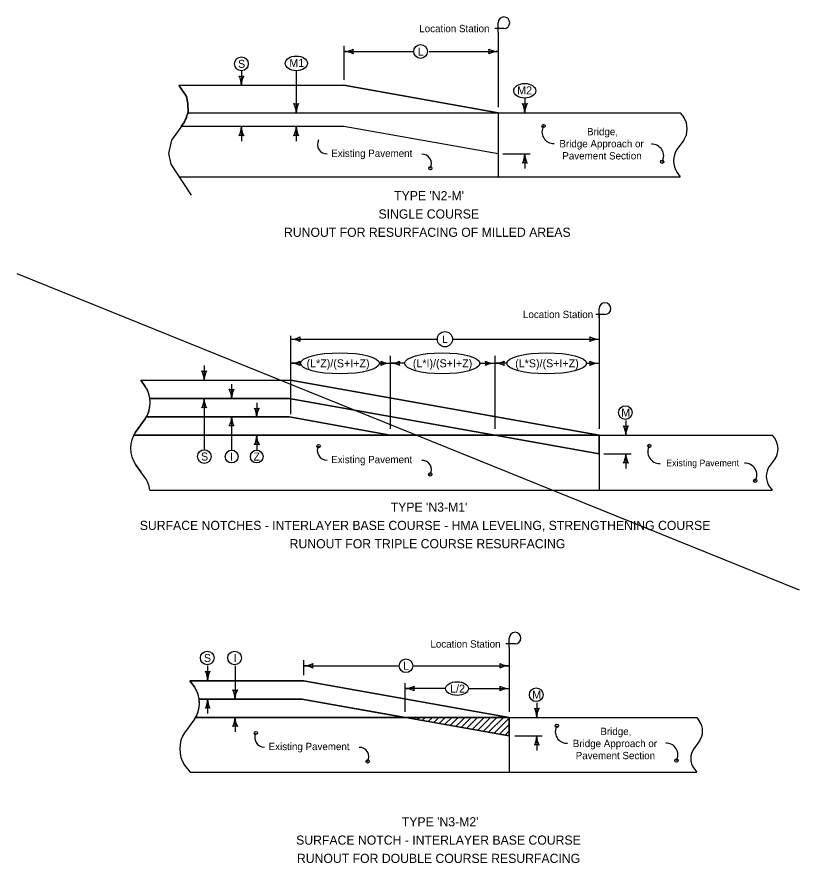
# Model space of a CAD drawing. Extents: x 10133 to 81668, y 2218 to 11018.
# Drawn here: x 14300 to 16011, y 5339 to 7189 of the extents above; entities that cross this region are included whole.
import ezdxf

# ---------------------------------------------------------------- set-up
doc = ezdxf.new("R2010")
doc.units = 0
for name, color, linetype in [('Default', 7, 'Continuous'), ('dsnNonPlotable', 7, 'Continuous'), ('dsnShtPlotShapeBatchPrint', 7, 'Continuous'), ('dsnStdBlock', 7, 'Continuous'), ('dsnStdBlockNotModified', 7, 'Continuous'), ('Level 2', 7, 'Continuous'), ('SheetBorder', 7, 'Continuous')]:
    doc.layers.add(name, color=color, linetype=linetype)

msp = doc.modelspace()

# ---------------------------------------------------------------- linework, layer by layer
at = {"layer": 'Default'}
for points in [[(14688, 5724.1), (14678.2, 5737.5), (14926.8, 5737.5), (15376.8, 5657.5), (15148.3, 5657.5), (14923.3, 5697.5), (14698.2, 5697.5)], [(15150.3, 5657.1), (15376.8, 5616.9), (15376.8, 5657.5), (15150.6, 5657.5), (15150.3, 5657.1)]]:
    msp.add_lwpolyline(points, dxfattribs=at)
msp.add_ellipse((14662.1, 5688.7), major_axis=(0, -50), ratio=0.732645, start_param=1.746494, end_param=2.356194, dxfattribs=at)
at = {"layer": 'dsnNonPlotable'}
for p, q in [((14580.4, 6381.2), (14570.6, 6394.6)), ((14570.6, 6394.6), (14898.5, 6394.6)), ((14898.5, 6394.6), (15573.5, 6274.6)), ((14895, 6354.6), (14590.5, 6354.6)), ((14590.5, 6354.6), (14590.6, 6354.6)), ((14590.5, 6354.6), (14895, 6354.6)), ((15345, 6274.6), (14895, 6354.6)), ((14895, 6354.6), (15345, 6274.6)), ((14559, 6281.2), (14580.4, 6310.5)), ((14580.4, 6310.5), (14580.4, 6310.5)), ((14895, 6314.6), (14583.1, 6314.6)), ((14583.1, 6314.6), (14895, 6314.6)), ((15116.5, 6274.6), (14895, 6314.6)), ((14895, 6314.6), (15116.5, 6274.6)), ((15116.5, 6274.6), (14554.9, 6274.6)), ((15345, 6274.6), (15116.5, 6274.6)), ((15573.5, 6274.6), (15345, 6274.6))]:
    msp.add_line(p, q, dxfattribs=at)
msp.add_lwpolyline([(14666.4, 6959.6), (14674.1, 6980.4), (14673.8, 6999.6), (14670.5, 7015), (14653.9, 7039.6), (15015, 7039.6), (15352.5, 6979.6), (15352.5, 6889.6), (15015, 6949.6), (14659.2, 6949.6)], close=True, dxfattribs=at)
for points in [[(15345, 6274.6), (15573.5, 6234), (15573.5, 6274.6), (15347.3, 6274.6), (15345, 6274.6)], [(14698.2, 5697.5), (14923.3, 5697.5), (15148.3, 5657.5), (14690.7, 5657.5)]]:
    msp.add_lwpolyline(points, dxfattribs=at)
for centre, major_axis, start_param, end_param in [((14554.5, 6345.9), (0, -50), 1.746494, 2.356194), ((14554.5, 6345.9), (0, -50), 0.895403, 1.746494), ((14554.5, 6345.9), (0, -50), 0.785398, 0.895403), ((14584.9, 6245.9), (0, 50), 0.785398, 0.958442), ((14662.1, 5688.7), (0, -50), 0.895403, 1.746494)]:
    msp.add_ellipse(centre, major_axis=major_axis, ratio=0.732645, start_param=start_param, end_param=end_param, dxfattribs=at)
at = {"layer": 'dsnStdBlock'}
for p, q in [((15365.2, 7163.8), (15344.9, 7163.8)), ((15352.5, 7156.1), (15352.5, 7176.5)), ((15352.5, 7156.1), (15352.5, 6991.6)), ((15015, 7125.6), (15015, 7051.6)), ((15015, 7113.6), (15166.3, 7113.6)), ((15201.3, 7113.6), (15352.5, 7113.6)), ((14790.7, 7071.6), (14790.7, 7039.6)), ((14910.7, 7071.6), (14910.7, 6979.6)), ((14653.9, 7039.6), (15015, 7039.6)), ((15352.5, 6979.6), (15015, 7039.6)), ((15410.7, 7011.6), (15410.7, 6979.6)), ((14673.5, 6979.6), (15015, 6979.6)), ((15352.5, 6979.6), (15352.5, 6839.6)), ((15352.5, 6979.6), (15751, 6979.6)), ((15352.5, 6979.6), (15352.5, 6839.6)), ((15751, 6979.6), (15758.5, 6969.3)), ((15015, 6949.6), (14659.2, 6949.6)), ((14790.7, 6949.6), (14790.7, 6917.6)), ((14910.7, 6949.6), (14910.7, 6917.6)), ((15352.5, 6889.6), (15015, 6949.6)), ((15758.5, 6919.8), (15743.5, 6899.3)), ((15362.7, 6889.6), (15422.7, 6889.6)), ((15410.7, 6889.6), (15410.7, 6857.6)), ((15743.5, 6849.8), (15751, 6839.6)), ((14653.9, 6839.6), (15751, 6839.6)), ((15573.5, 6530.9), (15573.5, 6551.3)), ((15586.2, 6538.6), (15565.9, 6538.6)), ((15573.5, 6538.6), (15573.5, 6288.4)), ((14898.5, 6491.5), (14898.5, 6400.6)), ((14899.6, 6484.4), (15219.4, 6484.4)), ((15252.7, 6484.4), (15573.5, 6484.4)), ((15116.5, 6448.4), (15116.5, 6288.4)), ((15345, 6448.4), (15345, 6288.4)), ((14709.3, 6426.9), (14709.3, 6394.9)), ((14920.1, 6431.7), (14898.5, 6431.7)), ((15092.7, 6431.7), (15116.5, 6431.7)), ((15147.9, 6431.7), (15116.5, 6431.7)), ((15312.3, 6431.7), (15345, 6431.7)), ((15371.3, 6431.7), (15345, 6431.7)), ((15545.8, 6431.7), (15573.5, 6431.7)), ((14570.6, 6394.6), (14580.4, 6381.2)), ((14570.6, 6394.6), (14898.5, 6394.6)), ((14769.2, 6386.3), (14769.2, 6354.3)), ((14898.5, 6400.6), (14898.5, 6320.4)), ((15573.5, 6274.6), (14898.5, 6394.6)), ((14590.5, 6354.6), (14895, 6354.6)), ((14709.3, 6354.6), (14709.3, 6242.5)), ((15573.5, 6234), (14895, 6354.6)), ((14824.2, 6345.2), (14824.2, 6313.2)), ((14580.4, 6310.5), (14559, 6281.2)), ((14583.1, 6314.6), (14895, 6314.6)), ((14769.3, 6315), (14769.3, 6241.9)), ((15116.5, 6274.6), (14895, 6314.6)), ((15631.7, 6306.6), (15631.7, 6274.6)), ((14554.9, 6274.6), (15951.9, 6274.6)), ((14824.3, 6273.9), (14824.3, 6241.9)), ((15345, 6274.6), (15345, 6274.6)), ((15345, 6274.6), (15573.5, 6274.6)), ((15345.7, 6274.5), (15345.9, 6274.6)), ((15346.9, 6274.3), (15347.3, 6274.6)), ((15348.5, 6274.6), (15903, 6274.6)), ((15350.5, 6273.6), (15351.4, 6274.6)), ((15573.5, 6274.6), (15573.5, 6234)), ((15951.9, 6274.6), (15958.4, 6265.8)), ((15573.5, 6234), (15573.5, 6154.6)), ((15583.7, 6234), (15643.7, 6234)), ((15631.7, 6234), (15631.7, 6202)), ((15958.4, 6223.4), (15945.5, 6205.8)), ((14580.4, 6181.2), (14559, 6210.6)), ((14559, 6210.5), (14571, 6194.6)), ((15945.5, 6163.4), (15951.9, 6154.6)), ((14590.6, 6154.6), (15951.9, 6154.6)), ((15376.8, 5810.5), (15376.8, 5830.8)), ((15389.5, 5818.1), (15369.2, 5818.1)), ((15376.8, 5810.5), (15376.8, 5669.5)), ((14926.8, 5782.5), (14926.8, 5749.5)), ((14716.8, 5769.9), (14716.8, 5737.9)), ((14776.8, 5769.9), (14776.8, 5697.5)), ((14926.8, 5770.5), (15135.8, 5770.5)), ((15165.8, 5770.5), (15376.8, 5770.5)), ((14678.2, 5737.5), (14688, 5724.1)), ((14678.2, 5737.5), (14926.8, 5737.5)), ((14927.3, 5737.4), (14678.2, 5737.5)), ((15376.8, 5657.5), (14926.8, 5737.5)), ((15148.3, 5732.5), (15148.3, 5669.5)), ((15237.6, 5720.5), (15148.3, 5720.5)), ((15287.6, 5720.5), (15376.8, 5720.5)), ((14698.2, 5697.5), (14923.3, 5697.5)), ((14716.8, 5697.9), (14716.8, 5665.9)), ((15376.8, 5616.9), (14923.3, 5697.5)), ((15436.8, 5689.5), (15436.8, 5657.5)), ((14688, 5653.4), (14666.5, 5624.1)), ((14690.7, 5657.5), (15376.8, 5657.5)), ((14776.8, 5657.9), (14776.8, 5625.9)), ((15148.3, 5657.5), (15148.3, 5657.5)), ((15148.3, 5657.5), (15376.8, 5657.5)), ((15149.1, 5657.3), (15149.2, 5657.5)), ((15150.3, 5657.1), (15150.6, 5657.5)), ((15163.4, 5654.8), (15166.1, 5657.5)), ((15168.2, 5653.9), (15171.7, 5657.5)), ((15175.4, 5652.7), (15180.2, 5657.5)), ((15186.2, 5650.7), (15193, 5657.5)), ((15199.4, 5648.4), (15208.5, 5657.5)), ((15211.4, 5646.3), (15222.7, 5657.5)), ((15223.4, 5644.1), (15236.8, 5657.5)), ((15235.4, 5642), (15250.9, 5657.5)), ((15247.5, 5639.9), (15265.1, 5657.5)), ((15259.5, 5637.7), (15279.2, 5657.5)), ((15271.5, 5635.6), (15293.4, 5657.5)), ((15283.5, 5633.5), (15307.5, 5657.5)), ((15295.5, 5631.3), (15321.6, 5657.5)), ((15307.5, 5629.2), (15335.8, 5657.5)), ((15319.5, 5627), (15349.9, 5657.5)), ((15331.5, 5624.9), (15364.1, 5657.5)), ((15343.5, 5622.8), (15376.8, 5656.1)), ((15376.8, 5657.5), (15786.8, 5657.5)), ((15376.8, 5657.5), (15376.8, 5616.9)), ((15786.8, 5657.5), (15793.3, 5648.7)), ((15355.5, 5620.6), (15376.8, 5642)), ((15367.5, 5618.5), (15376.8, 5627.8)), ((15376.8, 5616.9), (15376.8, 5537.5)), ((15388.8, 5616.9), (15448.8, 5616.9)), ((15436.8, 5616.9), (15436.8, 5584.9)), ((15793.3, 5606.3), (15780.4, 5588.7)), ((14666.5, 5553.4), (14678.5, 5537.5)), ((14678.5, 5537.5), (15786.8, 5537.5)), ((15780.4, 5546.3), (15786.8, 5537.5))]:
    msp.add_line(p, q, dxfattribs=at)
for points in [[(14653.9, 7039.6), (14670.5, 7015), (14673.8, 6999.6), (14674.1, 6980.4), (14666.4, 6959.6), (14652.9, 6940.8), (14638.1, 6919.6), (14631.5, 6890.8), (14636, 6866.9), (14680.9, 6799.6)], [(14673.5, 6979.6), (15352.5, 6979.6), (15352.5, 6889.6), (15015, 6949.6), (14659.3, 6949.6), (14663.7, 6955.5), (14663.7, 6955.5)]]:
    msp.add_lwpolyline(points, dxfattribs=at)
for points in [[(15345, 6274.6), (15573.5, 6274.6), (15573.5, 6234)], [(15148.3, 5657.5), (15376.8, 5657.5), (15376.8, 5616.9)]]:
    msp.add_lwpolyline(points, close=True, dxfattribs=at)
for centre, radius in [((15182.8, 7113.6), 15), ((14790.7, 7086.6), 15), ((15451.7, 6950.6), 3.56), ((15711.1, 6872.4), 3.56), ((15204.1, 6858.3), 3.56), ((15236, 6484.4), 16.6), ((15630.7, 6324.1), 15), ((14959.5, 6250.8), 3.56), ((15683.2, 6251.2), 3.56), ((14709.6, 6227.9), 15), ((14769.3, 6227.9), 14), ((14824.3, 6227.9), 14), ((15203.9, 6188.8), 3.56), ((15914.9, 6175), 3.56), ((14716, 5787.4), 15), ((14775.7, 5787.4), 15), ((15150.8, 5770.5), 15), ((15435.8, 5707), 15), ((14822.5, 5623.3), 3.56), ((15481, 5639.2), 3.56), ((15066.9, 5561.3), 3.56), ((15742.4, 5563), 3.56)]:
    msp.add_circle(centre, radius, dxfattribs=at)
for centre, radius, start, end in [((15365.2, 7176.5), 12.7, 270, 180), ((15015, 7156.7), 43.2, 270, 298.0725), ((15015, 7070.4), 43.2, 61.9275, 90), ((15051.2, 7113.6), 16.7, 162.2666, 197.7334), ((15316.3, 7113.6), 16.7, 342.2666, 17.7333), ((15352.5, 7156.7), 43.2, 241.9275, 270), ((15352.5, 7070.4), 43.2, 90, 118.0725), ((14790.7, 7075.8), 16.7, 252.2666, 287.7333), ((14747.5, 7039.6), 43.2, 360, 28.0725), ((14833.8, 7039.6), 43.2, 151.9275, 180), ((14910.7, 7015.8), 16.7, 252.2666, 287.7333), ((14867.5, 6979.6), 43.2, 360, 28.0725), ((14953.8, 6979.6), 43.2, 151.9275, 180), ((15410.7, 7015.8), 16.7, 252.2666, 287.7333), ((15367.5, 6979.6), 43.2, 360, 28.0725), ((15453.9, 6979.6), 43.2, 151.9275, 180), ((14747.5, 6949.6), 43.2, 331.9275, 360), ((14833.8, 6949.6), 43.2, 180, 208.0725), ((14867.5, 6949.6), 43.2, 331.9275, 360), ((14953.8, 6949.6), 43.2, 180, 208.0725), ((15473.9, 6937.9), 25.6, 150.0683, 272.8436), ((14790.7, 6913.4), 16.7, 72.2666, 107.7334), ((14910.7, 6913.4), 16.7, 72.2666, 107.7334), ((14977.4, 6910.1), 20.4, 150.0683, 272.8436), ((15689, 6885.2), 25.6, 330.0683, 92.8436), ((15186.4, 6868.5), 20.4, 330.0683, 92.8436), ((15367.5, 6889.6), 43.2, 331.9275, 360), ((15453.9, 6889.6), 43.2, 180, 208.0725), ((15410.7, 6853.4), 16.7, 72.2666, 107.7334), ((15586.2, 6551.3), 12.7, 270, 180), ((14898.5, 6527.5), 43.2, 270, 298.0725), ((14898.5, 6441.1), 43.2, 61.9275, 90), ((14934.7, 6484.3), 16.7, 162.2666, 197.7334), ((15537.3, 6484.4), 16.7, 342.2666, 17.7333), ((15573.5, 6527.6), 43.2, 241.9275, 270), ((15573.5, 6441.2), 43.2, 90, 118.0725), ((14898.5, 6474.9), 43.2, 270, 298.0725), ((14898.5, 6388.5), 43.2, 61.9275, 90), ((14934.7, 6431.7), 16.7, 162.2666, 197.7334), ((15080.3, 6431.7), 16.7, 342.2666, 17.7333), ((15116.5, 6474.9), 43.2, 241.9275, 270), ((15116.5, 6388.5), 43.2, 90, 118.0725), ((15116.5, 6474.9), 43.2, 270, 298.0725), ((15116.5, 6388.5), 43.2, 61.9275, 90), ((15152.7, 6431.7), 16.7, 162.2666, 197.7334), ((15308.8, 6431.7), 16.7, 342.2666, 17.7333), ((15345, 6474.9), 43.2, 241.9275, 270), ((15345, 6388.5), 43.2, 90, 118.0725), ((15345, 6474.9), 43.2, 270, 298.0725), ((15345, 6388.5), 43.2, 61.9275, 90), ((15381.2, 6431.7), 16.7, 162.2666, 197.7334), ((15537.3, 6431.7), 16.7, 342.2666, 17.7333), ((15573.5, 6474.9), 43.2, 241.9275, 270), ((15573.5, 6388.5), 43.2, 90, 118.0725), ((14709.3, 6431.1), 16.7, 252.2666, 287.7333), ((14666.1, 6394.9), 43.2, 360, 28.0725), ((14752.4, 6394.9), 43.2, 151.9275, 180), ((14769.3, 6390.8), 16.7, 252.2666, 287.7333), ((14726.1, 6354.6), 43.2, 360, 28.0725), ((14812.4, 6354.6), 43.2, 151.9275, 180), ((14666.1, 6354.6), 43.2, 331.9275, 360), ((14752.4, 6354.6), 43.2, 180, 208.0725), ((14709.3, 6318.4), 16.7, 72.2666, 107.7334), ((14824.3, 6349.7), 16.7, 252.2666, 287.7333), ((14781.1, 6313.5), 43.2, 360, 28.0725), ((14867.4, 6313.5), 43.2, 151.9275, 180), ((14726.1, 6315), 43.2, 331.9275, 360), ((14812.4, 6315), 43.2, 180, 208.0725), ((14769.3, 6278.8), 16.7, 72.2666, 107.7334), ((15631.7, 6310.8), 16.7, 252.2666, 287.7333), ((15588.6, 6274.6), 43.2, 360, 28.0725), ((15674.9, 6274.6), 43.2, 151.9275, 180), ((14781.1, 6273.9), 43.2, 331.9275, 360), ((14867.4, 6273.9), 43.2, 180, 208.0725), ((14824.3, 6237.7), 16.7, 72.2666, 107.7334), ((14977.2, 6240.6), 20.4, 150.0683, 272.8436), ((15705.3, 6238.5), 25.6, 150.0683, 272.8436), ((15186.2, 6199), 20.4, 330.0683, 92.8436), ((15588.6, 6234), 43.2, 331.9275, 360), ((15674.9, 6234), 43.2, 180, 208.0725), ((15631.7, 6197.8), 16.7, 72.2666, 107.7334), ((15892.7, 6187.7), 25.6, 330.0683, 92.8436), ((15389.5, 5830.8), 12.7, 270, 180), ((14926.8, 5813.7), 43.2, 270, 298.0725), ((14963, 5770.5), 16.7, 162.2666, 197.7334), ((15340.6, 5770.5), 16.7, 342.2666, 17.7333), ((15376.8, 5813.7), 43.2, 241.9275, 270), ((14716.8, 5774.1), 16.7, 252.2666, 287.7333), ((14673.7, 5737.9), 43.2, 360, 28.0725), ((14760, 5737.9), 43.2, 151.9275, 180), ((14926.8, 5727.3), 43.2, 61.9275, 90), ((15376.8, 5727.3), 43.2, 90, 118.0725), ((14776.8, 5733.7), 16.7, 252.2666, 287.7333), ((14733.7, 5697.5), 43.2, 360, 28.0725), ((14820, 5697.5), 43.2, 151.9275, 180), ((15148.3, 5763.7), 43.2, 270, 298.0725), ((15148.3, 5677.3), 43.2, 61.9275, 90), ((15184.5, 5720.5), 16.7, 162.2666, 197.7334), ((15340.6, 5720.5), 16.7, 342.2666, 17.7333), ((15376.8, 5763.7), 43.2, 241.9275, 270), ((15376.8, 5677.3), 43.2, 90, 118.0725), ((14673.7, 5697.9), 43.2, 331.9275, 360), ((14760, 5697.9), 43.2, 180, 208.0725), ((14716.8, 5661.7), 16.7, 72.2666, 107.7334), ((15436.8, 5693.7), 16.7, 252.2666, 287.7333), ((15393.7, 5657.5), 43.2, 360, 28.0725), ((15480, 5657.5), 43.2, 151.9275, 180), ((14733.7, 5657.9), 43.2, 331.9275, 360), ((14820, 5657.9), 43.2, 180, 208.0725), ((14776.8, 5621.7), 16.7, 72.2666, 107.7334), ((15503.1, 5626.4), 25.6, 150.0683, 272.8436), ((14840.2, 5613.1), 20.4, 150.0683, 272.8436), ((15393.7, 5616.9), 43.2, 331.9275, 360), ((15480, 5616.9), 43.2, 180, 208.0725), ((15049.2, 5571.5), 20.4, 330.0683, 92.8436), ((15436.8, 5580.7), 16.7, 72.2666, 107.7334), ((15720.2, 5575.7), 25.6, 330.0683, 92.8436)]:
    msp.add_arc(centre, radius, start, end, dxfattribs=at)
for centre, major_axis, ratio in [((14910.7, 7087.6), (-24.3, 0), 0.658717), ((15410.7, 7027.6), (-24.3, 0), 0.658717), ((15006.4, 6431.7), (86.3, 0), 0.266932), ((15230.1, 6431.7), (82.2, 0), 0.280198), ((15458.6, 6431.7), (87.3, 0), 0.264007), ((15262.6, 5720.5), (25, 0), 0.6)]:
    msp.add_ellipse(centre, major_axis=major_axis, ratio=ratio, dxfattribs=at)
for centre, major_axis, ratio, start_param, end_param in [((14637.8, 6990.8), (0, -50), 0.732645, 0.785398, 1.343633), ((15740.4, 6944.6), (0, -35), 0.732627, 0.785398, 2.356194), ((15761.7, 6874.6), (0, 35), 0.732627, 0.785398, 2.356194), ((14554.5, 6345.9), (0, -50), 0.732645, 0.785398, 2.356194), ((14584.9, 6245.9), (0, 50), 0.732645, 0.785398, 2.356194), ((15942.8, 6244.6), (0, -30), 0.732645, 0.785398, 2.356194), ((15961.1, 6184.6), (0, 30), 0.732645, 0.785398, 2.356194), ((14554.5, 6145.9), (0, 50), 0.732645, 4.888087, 5.497787), ((14662.1, 5688.7), (0, -50), 0.732645, 0.785398, 2.356194), ((15777.7, 5627.5), (0, -30), 0.732645, 0.785398, 2.356194), ((14692.4, 5588.7), (0, 50), 0.732645, 0.785398, 2.356194), ((15795.9, 5567.5), (0, 30), 0.732645, 0.785398, 2.356194)]:
    msp.add_ellipse(centre, major_axis=major_axis, ratio=ratio, start_param=start_param, end_param=end_param, dxfattribs=at)
at = {"layer": 'SheetBorder'}
msp.add_line((14299.6, 6628.2), (16010.8, 5936.1), dxfattribs=at)

# ---------------------------------------------------------------- texts
at = {"layer": 'dsnShtPlotShapeBatchPrint'}
for s, height, p in [('(L*Z)/(S+I+Z)', 17.5, (14933.3, 6423)), ('(L*I)/(S+I+Z)', 17.5, (15165.8, 6423)), ('(L*S)/(S+I+Z)', 17.5, (15389.7, 6423)), ('M', 17.5, (15621.8, 6315.4)), ('S', 17.5, (14702.3, 6219.2)), ('S', 17.5, (14708.7, 5778.6)), ('I', 17.5, (14773.5, 5778.6)), ('L', 17.5, (15144.6, 5761.7)), ('L/2', 17.5, (15247.4, 5711.7)), ('M', 17.5, (15426.9, 5698.2)), ('Bridge,', 16, (15576.1, 5618.9)), ('Bridge Approach or', 16, (15515.7, 5592.5)), ('Pavement Section', 16, (15522.1, 5566.1))]:
    msp.add_text(s, height=height, dxfattribs=at).set_placement(p)
at = {"layer": 'dsnStdBlockNotModified'}
for s, height, p in [('Location Station', 16, (15179.9, 7155.8)), ('L', 17.5, (15176.5, 7104.8)), ('S', 17.5, (14783.4, 7077.8)), ('M1', 17.5, (14895.5, 7079.8)), ('M2', 17.5, (15394.1, 7019.8)), ('Bridge,', 16, (15546.9, 6930.3)), ('Bridge Approach or', 16, (15486.5, 6903.9)), ('Existing Pavement', 16, (14987.4, 6882.9)), ('Pavement Section', 16, (15492.8, 6877.5)), ("TYPE 'N2-M'", 20, (15124.9, 6788.3)), ('SINGLE COURSE', 20, (15090.7, 6748.3)), ('RUNOUT FOR RESURFACING OF MILLED AREAS', 20, (14883.9, 6708.3)), ('Location Station', 16, (15406.8, 6530.6)), ('L', 15.8, (15230.4, 6476.5)), ('I', 17.5, (14766.1, 6219.2)), ('Z', 17.5, (14817.2, 6219.2)), ('Existing Pavement', 16, (14987.2, 6213.4)), ('Existing Pavement', 14.4, (15720.1, 6206.7)), ('Location Station', 16, (15204.2, 5810.1)), ('Existing Pavement', 16, (14850.2, 5585.9))]:
    msp.add_text(s, height=height, dxfattribs=at).set_placement(p)
at = {"layer": 'Level 2'}
for s, p in [("TYPE 'N3-M1'", (15117.4, 6107.3)), ('SURFACE NOTCHES - INTERLAYER BASE COURSE - HMA LEVELING, STRENGTHENING COURSE', (14568.4, 6067.3)), ('RUNOUT FOR TRIPLE COURSE RESURFACING', (14896.2, 6027.3)), ("TYPE 'N3-M2'", (15141.7, 5419.2)), ('SURFACE NOTCH - INTERLAYER BASE COURSE', (14910.5, 5379.2)), ('RUNOUT FOR DOUBLE COURSE RESURFACING', (14912.2, 5339.2))]:
    msp.add_text(s, height=20, dxfattribs=at).set_placement(p)

doc.saveas('drawing.dxf')
